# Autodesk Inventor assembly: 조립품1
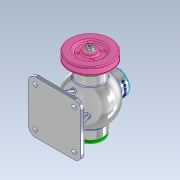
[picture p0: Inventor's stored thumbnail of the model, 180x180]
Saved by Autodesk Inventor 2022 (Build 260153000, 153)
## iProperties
Created: 2024-04
Part Number: 조립품1
Document SubType Name: Assembly
Designer: Admin
Author: Admin
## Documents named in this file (16)
- C:\Users\Admin\Desktop\740406V1003\조립품1.iam
- C:\Users\Admin\Desktop\740406V1003\본체.ipt
- C:\Users\Admin\Desktop\740406V1003\뒤커버.ipt
- C:\Users\Admin\Desktop\740406V1003\앞커버.ipt
- C:\Users\Admin\Desktop\740406V1003\상부커버.ipt
- C:\Users\Admin\Desktop\740406V1003\베어링- 6202.ipt
- KS B 2023 - 6202 - 15 x 35 x 11 - 7.8.ipt
- C:\Users\Admin\Desktop\740406V1003\칼라.ipt
- C:\Users\Admin\Desktop\740406V1003\편심축.ipt
- C:\Users\Admin\Desktop\740406V1003\키 4 x 4 x 12.ipt
- C:\Users\Admin\Desktop\740406V1003\오일실 15 30 7.ipt
- C:\Users\Admin\Desktop\740406V1003\V-벨트풀리.ipt
- C:\Users\Admin\Desktop\740406V1003\너트 M8.ipt
- C:\Users\Admin\Desktop\740406V1003\볼트 M4 x 16.ipt
- C:\Users\Admin\Desktop\740406V1003\볼트 M4 x 12.ipt
- C:\Users\Admin\Desktop\740406V1003\슬라이드.ipt
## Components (15 placed, 4 different names)
1. KS B 2023 - 6202 - 15 x 35 x 11 - 7.8:1
2. KS B 2023 - 6202 - 15 x 35 x 11 - 7.8:2
3. V-벨트풀리:1
4. ISO 4762 M4 x 16:1
5. ISO 4762 M4 x 16:2
6. ISO 4762 M4 x 16:3
7. ISO 4762 M4 x 16:4
8. ISO 4762 M4 x 16:5
9. ISO 4762 M4 x 16:6
10. ISO 4762 M4 x 16:7
11. ISO 4762 M4 x 16:8
12. KS B 1021 - 에 따름 ISO 1207 - 미터 A  M 4 x 12:1
13. KS B 1021 - 에 따름 ISO 1207 - 미터 A  M 4 x 12:2
14. KS B 1021 - 에 따름 ISO 1207 - 미터 A  M 4 x 12:3
15. KS B 1021 - 에 따름 ISO 1207 - 미터 A  M 4 x 12:4
